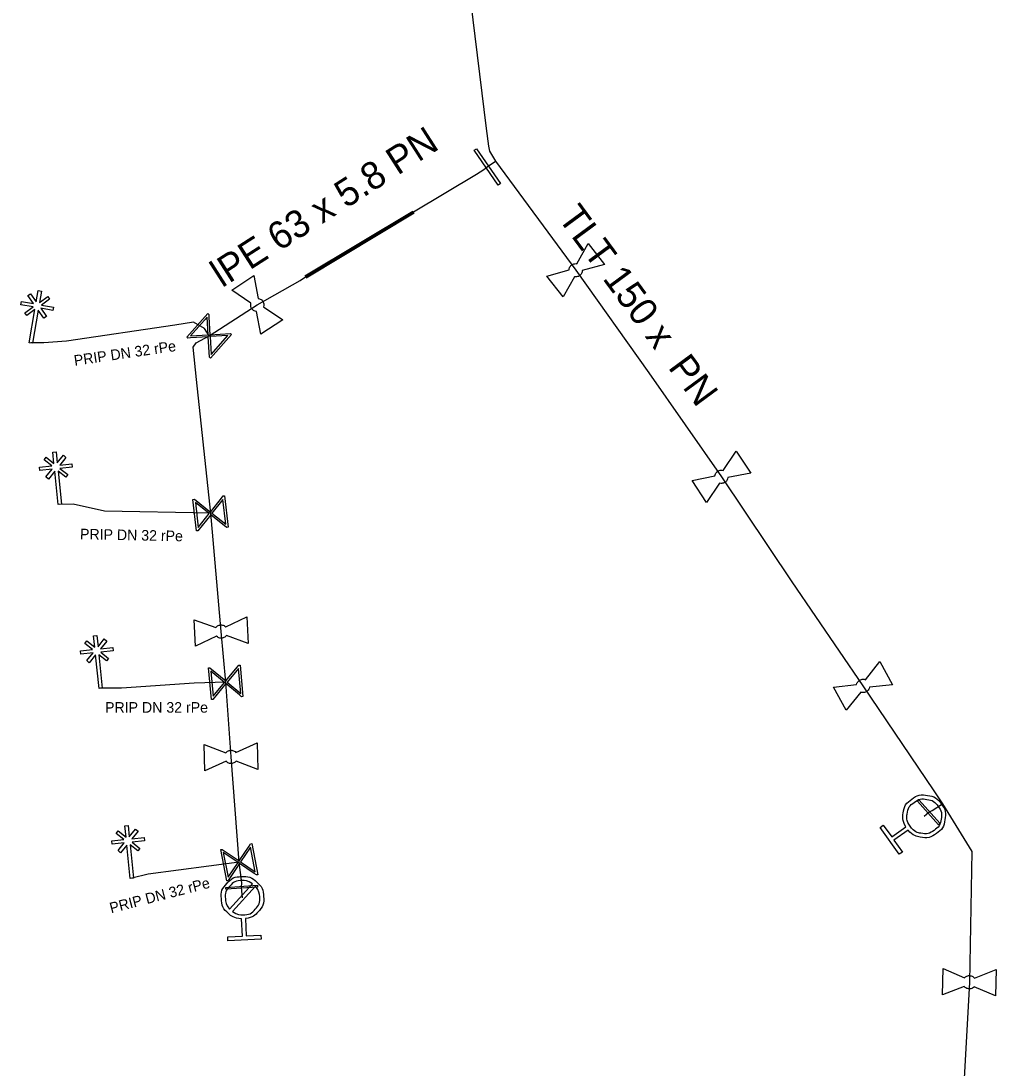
# Model space of a CAD drawing. Extents: x -643842 to -636370, y -1119190 to -1110210.
# Drawn here: x -640840.53 to -640794.41, y -1114656.76 to -1114607.23 of the extents above; entities that cross this region are included whole.
import ezdxf

# ---------------------------------------------------------------- set-up
doc = ezdxf.new("R2010")
doc.units = 0
for name, color, linetype in [('2', 7, 'Continuous'), ('22', 7, 'Continuous'), ('Default', 7, 'Continuous'), ('Level 16', 7, 'Continuous'), ('Level 20', 7, 'Continuous'), ('Level 21', 7, 'Continuous'), ('Level 23', 7, 'Continuous'), ('Level 28', 7, 'Continuous'), ('Level 29', 7, 'Continuous'), ('Level 30', 7, 'Continuous'), ('Level 33', 7, 'Continuous')]:
    doc.layers.add(name, color=color, linetype=linetype)

msp = doc.modelspace()

# ---------------------------------------------------------------- linework, layer by layer
at = {"layer": '2'}
for points in [[(-640839.801, -1114620.515), (-640839.709, -1114619.984), (-640839.555, -1114620.01), (-640839.646, -1114620.537), (-640839.263, -1114620.266), (-640839.174, -1114620.394), (-640839.554, -1114620.663), (-640838.986, -1114620.761), (-640839.013, -1114620.915), (-640839.59, -1114620.816), (-640839.316, -1114621.202), (-640839.443, -1114621.292), (-640839.711, -1114620.914), (-640839.981, -1114622.474), (-640840.135, -1114622.447), (-640839.864, -1114620.882), (-640840.25, -1114621.155), (-640840.339, -1114621.027), (-640839.952, -1114620.753), (-640840.528, -1114620.653), (-640840.502, -1114620.499), (-640839.935, -1114620.597), (-640840.202, -1114620.218), (-640840.075, -1114620.129), (-640839.801, -1114620.515)], [(-640838.968, -1114628.158), (-640839.024, -1114627.621), (-640838.869, -1114627.605), (-640838.813, -1114628.137), (-640838.519, -1114627.772), (-640838.398, -1114627.872), (-640838.69, -1114628.233), (-640838.117, -1114628.174), (-640838.101, -1114628.329), (-640838.684, -1114628.39), (-640838.315, -1114628.688), (-640838.413, -1114628.808), (-640838.774, -1114628.517), (-640838.61, -1114630.092), (-640838.765, -1114630.108), (-640838.93, -1114628.528), (-640839.226, -1114628.895), (-640839.347, -1114628.796), (-640839.049, -1114628.428), (-640839.631, -1114628.488), (-640839.647, -1114628.333), (-640839.075, -1114628.273), (-640839.435, -1114627.981), (-640839.337, -1114627.86), (-640838.968, -1114628.158)], [(-640837.038, -1114636.848), (-640837.094, -1114636.311), (-640836.939, -1114636.295), (-640836.883, -1114636.827), (-640836.589, -1114636.462), (-640836.468, -1114636.562), (-640836.76, -1114636.923), (-640836.187, -1114636.864), (-640836.171, -1114637.019), (-640836.754, -1114637.08), (-640836.385, -1114637.378), (-640836.483, -1114637.498), (-640836.844, -1114637.207), (-640836.68, -1114638.782), (-640836.835, -1114638.798), (-640837, -1114637.218), (-640837.296, -1114637.585), (-640837.417, -1114637.486), (-640837.119, -1114637.118), (-640837.701, -1114637.178), (-640837.717, -1114637.023), (-640837.145, -1114636.963), (-640837.505, -1114636.671), (-640837.407, -1114636.55), (-640837.038, -1114636.848)], [(-640835.558, -1114645.838), (-640835.614, -1114645.301), (-640835.459, -1114645.285), (-640835.403, -1114645.817), (-640835.109, -1114645.452), (-640834.988, -1114645.552), (-640835.28, -1114645.913), (-640834.707, -1114645.854), (-640834.691, -1114646.009), (-640835.274, -1114646.07), (-640834.905, -1114646.368), (-640835.003, -1114646.488), (-640835.364, -1114646.197), (-640835.2, -1114647.772), (-640835.355, -1114647.788), (-640835.52, -1114646.208), (-640835.816, -1114646.575), (-640835.937, -1114646.476), (-640835.639, -1114646.108), (-640836.221, -1114646.168), (-640836.237, -1114646.013), (-640835.665, -1114645.953), (-640836.025, -1114645.661), (-640835.927, -1114645.54), (-640835.558, -1114645.838)]]:
    msp.add_lwpolyline(points, dxfattribs=at)
at = {"layer": 'Default'}
for points in [[(-640814.602, -1114619.006), (-640814.6, -1114618.953), (-640814.579, -1114618.902), (-640814.547, -1114618.825), (-640814.483, -1114618.774), (-640814.418, -1114618.724), (-640814.333, -1114618.711), (-640814.28, -1114618.702), (-640814.228, -1114618.713)], [(-640813.976, -1114619.034), (-640813.979, -1114619.086), (-640813.999, -1114619.136), (-640814.033, -1114619.215), (-640814.097, -1114619.266), (-640814.161, -1114619.316), (-640814.245, -1114619.329), (-640814.299, -1114619.337), (-640814.351, -1114619.327)], [(-640829.391, -1114620.972), (-640829.442, -1114620.964), (-640829.49, -1114620.94), (-640829.566, -1114620.9), (-640829.611, -1114620.831), (-640829.656, -1114620.763), (-640829.662, -1114620.679), (-640829.665, -1114620.625), (-640829.65, -1114620.574)], [(-640829.31, -1114620.35), (-640829.257, -1114620.357), (-640829.209, -1114620.382), (-640829.134, -1114620.42), (-640829.089, -1114620.489), (-640829.044, -1114620.557), (-640829.038, -1114620.644), (-640829.034, -1114620.696), (-640829.049, -1114620.747)], [(-640807.71, -1114628.751), (-640807.704, -1114628.698), (-640807.679, -1114628.65), (-640807.641, -1114628.575), (-640807.573, -1114628.529), (-640807.504, -1114628.484), (-640807.418, -1114628.478), (-640807.365, -1114628.474), (-640807.314, -1114628.489)], [(-640807.088, -1114628.83), (-640807.095, -1114628.881), (-640807.119, -1114628.929), (-640807.159, -1114629.005), (-640807.227, -1114629.051), (-640807.296, -1114629.096), (-640807.38, -1114629.102), (-640807.434, -1114629.105), (-640807.485, -1114629.091)], [(-640831.307, -1114635.919), (-640831.275, -1114635.877), (-640831.229, -1114635.847), (-640831.158, -1114635.802), (-640831.076, -1114635.798), (-640830.995, -1114635.794), (-640830.917, -1114635.832), (-640830.869, -1114635.855), (-640830.833, -1114635.894)], [(-640830.812, -1114636.302), (-640830.844, -1114636.343), (-640830.889, -1114636.372), (-640830.962, -1114636.418), (-640831.044, -1114636.422), (-640831.125, -1114636.426), (-640831.201, -1114636.389), (-640831.25, -1114636.364), (-640831.286, -1114636.326)], [(-640801.006, -1114638.615), (-640800.995, -1114638.564), (-640800.966, -1114638.517), (-640800.922, -1114638.445), (-640800.85, -1114638.406), (-640800.779, -1114638.367), (-640800.692, -1114638.368), (-640800.639, -1114638.368), (-640800.589, -1114638.387)], [(-640800.393, -1114638.745), (-640800.404, -1114638.796), (-640800.431, -1114638.842), (-640800.478, -1114638.915), (-640800.55, -1114638.954), (-640800.621, -1114638.993), (-640800.705, -1114638.992), (-640800.76, -1114638.992), (-640800.809, -1114638.973)], [(-640830.832, -1114641.842), (-640830.799, -1114641.801), (-640830.752, -1114641.773), (-640830.68, -1114641.73), (-640830.598, -1114641.728), (-640830.516, -1114641.725), (-640830.44, -1114641.766), (-640830.393, -1114641.791), (-640830.357, -1114641.83)], [(-640830.347, -1114642.239), (-640830.38, -1114642.279), (-640830.425, -1114642.307), (-640830.5, -1114642.35), (-640830.582, -1114642.352), (-640830.664, -1114642.355), (-640830.738, -1114642.315), (-640830.786, -1114642.289), (-640830.821, -1114642.25)], [(-640798.675, -1114645.353), (-640798.859, -1114645.044), (-640798.797, -1114644.683), (-640798.727, -1114644.276), (-640798.389, -1114644.034), (-640798.051, -1114643.794), (-640797.644, -1114643.863), (-640797.236, -1114643.933), (-640796.994, -1114644.271), (-640796.755, -1114644.607), (-640796.823, -1114645.015), (-640796.891, -1114645.423), (-640797.228, -1114645.663), (-640797.567, -1114645.905), (-640797.974, -1114645.838), (-640798.337, -1114645.78), (-640798.568, -1114645.503)], [(-640798.472, -1114645.324), (-640798.276, -1114645.599), (-640797.945, -1114645.655), (-640797.614, -1114645.711), (-640797.339, -1114645.514), (-640797.064, -1114645.318), (-640797.008, -1114644.987), (-640796.953, -1114644.656), (-640797.149, -1114644.381), (-640797.344, -1114644.108), (-640797.675, -1114644.051), (-640798.007, -1114643.995), (-640798.282, -1114644.191), (-640798.557, -1114644.387), (-640798.613, -1114644.718), (-640798.668, -1114645.049), (-640798.472, -1114645.324)], [(-640830.094, -1114649.699), (-640830.454, -1114649.687), (-640830.724, -1114649.44), (-640831.029, -1114649.161), (-640831.049, -1114648.746), (-640831.069, -1114648.332), (-640830.79, -1114648.027), (-640830.511, -1114647.721), (-640830.096, -1114647.701), (-640829.684, -1114647.681), (-640829.378, -1114647.959), (-640829.071, -1114648.237), (-640829.051, -1114648.65), (-640829.031, -1114649.066), (-640829.308, -1114649.372), (-640829.553, -1114649.646), (-640829.911, -1114649.691)], [(-640829.573, -1114648.04), (-640829.798, -1114647.876), (-640830.087, -1114647.89), (-640830.422, -1114647.906), (-640830.649, -1114648.155), (-640830.876, -1114648.403), (-640830.86, -1114648.741), (-640830.846, -1114649.03), (-640830.662, -1114649.238)], [(-640830.527, -1114649.36), (-640830.302, -1114649.527), (-640830.009, -1114649.513), (-640829.672, -1114649.497), (-640829.446, -1114649.249), (-640829.22, -1114649), (-640829.236, -1114648.663), (-640829.25, -1114648.37), (-640829.438, -1114648.162)], [(-640795.902, -1114652.491), (-640795.867, -1114652.452), (-640795.819, -1114652.426), (-640795.745, -1114652.386), (-640795.663, -1114652.388), (-640795.582, -1114652.389), (-640795.507, -1114652.434), (-640795.461, -1114652.46), (-640795.428, -1114652.501)], [(-640795.436, -1114652.91), (-640795.471, -1114652.948), (-640795.518, -1114652.974), (-640795.595, -1114653.014), (-640795.677, -1114653.012), (-640795.758, -1114653.011), (-640795.831, -1114652.968), (-640795.878, -1114652.94), (-640795.911, -1114652.899)]]:
    msp.add_open_spline(points, degree=3, dxfattribs=at)
at = {"layer": 'Level 16'}
for points in [[(-640817.956, -1114614.99), (-640819.087, -1114613.341), (-640818.984, -1114613.27), (-640817.853, -1114614.919), (-640817.956, -1114614.99)], [(-640832.689, -1114622.183), (-640831.693, -1114621.061), (-640831.643, -1114621.105), (-640831.64, -1114621.233), (-640831.589, -1114622.072), (-640830.62, -1114622.014), (-640830.571, -1114622.057), (-640831.567, -1114623.179), (-640831.617, -1114623.135), (-640831.672, -1114622.165), (-640832.51, -1114622.216), (-640832.64, -1114622.226), (-640832.689, -1114622.183)], [(-640832.514, -1114622.127), (-640831.677, -1114622.077), (-640831.728, -1114621.242), (-640832.514, -1114622.127)], [(-640830.742, -1114622.109), (-640831.584, -1114622.16), (-640831.533, -1114622.999), (-640830.742, -1114622.109)], [(-640830.901, -1114629.689), (-640830.729, -1114631.179), (-640830.794, -1114631.187), (-640830.893, -1114631.104), (-640831.551, -1114630.582), (-640832.154, -1114631.343), (-640832.219, -1114631.351), (-640832.391, -1114629.861), (-640832.326, -1114629.853), (-640831.566, -1114630.459), (-640831.044, -1114629.8), (-640830.966, -1114629.697), (-640830.901, -1114629.689)], [(-640832.143, -1114631.189), (-640831.62, -1114630.528), (-640832.28, -1114630.006), (-640832.143, -1114631.189)], [(-640830.976, -1114629.856), (-640831.497, -1114630.513), (-640830.84, -1114631.033), (-640830.976, -1114629.856)], [(-640830.16, -1114637.696), (-640830.026, -1114639.19), (-640830.092, -1114639.196), (-640830.188, -1114639.111), (-640830.833, -1114638.573), (-640831.455, -1114639.318), (-640831.52, -1114639.324), (-640831.654, -1114637.83), (-640831.588, -1114637.824), (-640830.844, -1114638.449), (-640830.306, -1114637.803), (-640830.225, -1114637.702), (-640830.16, -1114637.696)], [(-640830.239, -1114637.861), (-640830.776, -1114638.505), (-640830.134, -1114639.041), (-640830.239, -1114637.861)], [(-640831.44, -1114639.164), (-640830.9, -1114638.516), (-640831.546, -1114637.977), (-640831.44, -1114639.164)], [(-640797.124, -1114645.249), (-640798.126, -1114644.133), (-640798.056, -1114644.071), (-640797.054, -1114645.187), (-640797.124, -1114645.249)], [(-640829.605, -1114646.142), (-640829.322, -1114647.615), (-640829.386, -1114647.627), (-640829.49, -1114647.552), (-640830.187, -1114647.082), (-640830.73, -1114647.886), (-640830.795, -1114647.898), (-640831.078, -1114646.425), (-640831.014, -1114646.413), (-640830.21, -1114646.959), (-640829.74, -1114646.263), (-640829.67, -1114646.154), (-640829.605, -1114646.142)], [(-640829.668, -1114646.314), (-640830.137, -1114647.009), (-640829.444, -1114647.477), (-640829.668, -1114646.314)], [(-640830.731, -1114647.731), (-640830.26, -1114647.032), (-640830.957, -1114646.562), (-640830.731, -1114647.731)], [(-640829.339, -1114648.209), (-640830.835, -1114648.305), (-640830.841, -1114648.211), (-640829.345, -1114648.115), (-640829.339, -1114648.209)]]:
    msp.add_lwpolyline(points, dxfattribs=at)
at = {"layer": 'Level 21'}
for points in [[(-640821.34, -1114587.39), (-640821.22, -1114588.48), (-640820.6, -1114594.38), (-640819.99, -1114600.31), (-640819.266, -1114606.266), (-640818.53, -1114612.31), (-640818.42, -1114613.15), (-640818.37, -1114613.38), (-640818.09, -1114613.86)], [(-640830.05, -1114648.7), (-640830.08, -1114648.38), (-640830.09, -1114648.21), (-640830.08, -1114648), (-640830.2, -1114647.02), (-640830.59, -1114642.04), (-640830.84, -1114638.51), (-640831.06, -1114636.11), (-640831.553, -1114630.512), (-640831.59, -1114630.09), (-640832.23, -1114624.19), (-640832.39, -1114622.65), (-640832.24, -1114622.46), (-640831.63, -1114622.12), (-640829.35, -1114620.66), (-640827.32, -1114619.51), (-640827.07, -1114619.33), (-640821.96, -1114616.26), (-640818.98, -1114614.47), (-640818.64, -1114614.25), (-640818.47, -1114614.13), (-640818.09, -1114613.86)], [(-640818.09, -1114613.86), (-640814.29, -1114619.02), (-640810.836, -1114623.872), (-640807.4, -1114628.79), (-640804.066, -1114633.752), (-640800.706, -1114638.671), (-640797.35, -1114643.64), (-640796.94, -1114644.26), (-640795.55, -1114646.51), (-640795.67, -1114652.7), (-640796, -1114658.68), (-640796.39, -1114664.93), (-640796.29, -1114665.2), (-640796.18, -1114665.5)], [(-640797.81, -1114644.85), (-640797.59, -1114644.66), (-640797.43, -1114644.57), (-640796.94, -1114644.26)]]:
    msp.add_lwpolyline(points, dxfattribs=at)
at = {"layer": 'Level 23'}
for points in [[(-640831.63, -1114622.12), (-640831.84, -1114621.78), (-640832.36, -1114621.47), (-640833.25, -1114621.62), (-640838.37, -1114622.37), (-640839.44, -1114622.46), (-640840.06, -1114622.46)], [(-640831.553, -1114630.512), (-640836.58, -1114630.41), (-640838.06, -1114630.08), (-640838.69, -1114630.1)], [(-640830.84, -1114638.51), (-640832.33, -1114638.56), (-640835.77, -1114638.79), (-640836.76, -1114638.79)], [(-640830.2, -1114647.02), (-640834.51, -1114647.58), (-640835.28, -1114647.78)]]:
    msp.add_lwpolyline(points, dxfattribs=at)
at = {"layer": 'Level 28'}
for points in [[(-640814.228, -1114618.713), (-640813.692, -1114617.757)], [(-640813.692, -1114617.757), (-640812.921, -1114618.74), (-640813.976, -1114619.034)], [(-640814.351, -1114619.327), (-640814.888, -1114620.283), (-640815.659, -1114619.3), (-640814.602, -1114619.006)], [(-640829.65, -1114620.574), (-640830.558, -1114619.958), (-640829.513, -1114619.272), (-640829.31, -1114620.35)], [(-640828.142, -1114621.362), (-640829.187, -1114622.048), (-640829.391, -1114620.972)], [(-640829.049, -1114620.747), (-640828.142, -1114621.362)], [(-640807.314, -1114628.489), (-640806.703, -1114627.579)], [(-640806.703, -1114627.579), (-640806.013, -1114628.621), (-640807.088, -1114628.83)], [(-640807.485, -1114629.091), (-640808.097, -1114630.001), (-640808.787, -1114628.959), (-640807.71, -1114628.751)], [(-640830.833, -1114635.894), (-640829.844, -1114635.42)], [(-640829.844, -1114635.42), (-640829.779, -1114636.669), (-640830.812, -1114636.302)], [(-640831.286, -1114636.326), (-640832.276, -1114636.8), (-640832.341, -1114635.551), (-640831.307, -1114635.919)], [(-640800.589, -1114638.387), (-640799.905, -1114637.53)], [(-640799.905, -1114637.53), (-640799.303, -1114638.626), (-640800.393, -1114638.745)], [(-640800.809, -1114638.973), (-640801.495, -1114639.83), (-640802.096, -1114638.734), (-640801.006, -1114638.615)], [(-640830.357, -1114641.83), (-640829.357, -1114641.382)], [(-640829.357, -1114641.382), (-640829.324, -1114642.632), (-640830.347, -1114642.239)], [(-640830.821, -1114642.25), (-640831.823, -1114642.698), (-640831.856, -1114641.448), (-640830.832, -1114641.842)], [(-640795.911, -1114652.899), (-640796.933, -1114653.298), (-640796.907, -1114652.049), (-640795.902, -1114652.491)], [(-640794.407, -1114652.102), (-640794.433, -1114653.351), (-640795.436, -1114652.91)], [(-640795.428, -1114652.501), (-640794.407, -1114652.102)]]:
    msp.add_lwpolyline(points, dxfattribs=at)
at = {"layer": 'Level 29'}
for points in [[(-640827.096, -1114619.287), (-640821.986, -1114616.217)], [(-640827.044, -1114619.373), (-640821.934, -1114616.303)]]:
    msp.add_lwpolyline(points, dxfattribs=at)
at = {"layer": 'Level 30'}
msp.add_lwpolyline([(-640821.96, -1114616.26), (-640827.07, -1114619.33)], dxfattribs=at)
at = {"layer": 'Level 33'}
for points in [[(-640798.568, -1114645.503), (-640799.236, -1114645.979), (-640798.836, -1114646.54), (-640798.986, -1114646.647), (-640799.892, -1114645.374), (-640799.743, -1114645.268), (-640799.343, -1114645.829), (-640798.675, -1114645.353)], [(-640830.662, -1114649.238), (-640829.573, -1114648.04)], [(-640829.438, -1114648.162), (-640830.527, -1114649.36)], [(-640829.911, -1114649.691), (-640829.871, -1114650.51), (-640829.183, -1114650.477), (-640829.174, -1114650.66), (-640830.735, -1114650.735), (-640830.743, -1114650.552), (-640830.055, -1114650.519), (-640830.094, -1114649.699)]]:
    msp.add_lwpolyline(points, dxfattribs=at)

# ---------------------------------------------------------------- texts
at = {"layer": '22'}
for rotation, p in [(8.3337, (-640837.984, -1114623.54)), (358.8376, (-640837.739, -1114631.745)), (14.5603, (-640836.261, -1114649.444))]:
    msp.add_text('PRIP DN 32 rPe', height=0.5, rotation=rotation, dxfattribs=at).set_placement(p)
msp.add_text('PRIP DN 32 rPe', height=0.5, dxfattribs=at).set_placement((-640836.55, -1114639.948))
at = {"layer": 'Level 20'}
for s, rotation, p in [('lPE 63 x 5.8 PN ', 32.6335, (-640831.013, -1114619.866)), ('TLT 150 x  PN ', 306.3692, (-640815.166, -1114616.536))]:
    msp.add_text(s, height=1.3, rotation=rotation, dxfattribs=at).set_placement(p)

doc.saveas('drawing.dxf')
